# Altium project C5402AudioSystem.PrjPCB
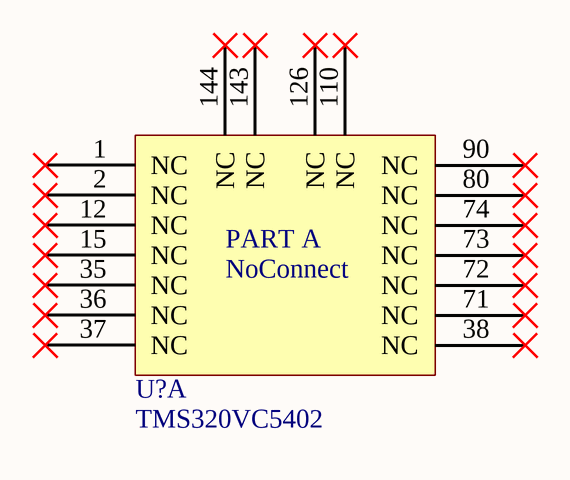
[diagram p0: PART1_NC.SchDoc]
5 sheets, 5 parts. Net scope: global (net labels, ports and power ports of the same name join across sheets).
Sheets:
  PART1_NC.SchDoc
  PART2_PowerSupply.SchDoc
  PART3_Memory.SchDoc
  PART4_Basic.SchDoc
  PART5_HPI_McBSP.SchDoc

## Sheet PART1_NC.SchDoc: 非连接件
size A4; Author: 崔 敖; 李尚文; SheetNumber: 1

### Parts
(Parts that share a designator on the sheet are numbered #1, #2 ... from top to bottom, then left to right.)
U?#1  TMS320VC5402  [TMS320VC5401_PQFP144]  (part A of 5)

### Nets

Not connected (* = marked no-connect by the designer): U?#1 1(NC)* 2(NC)* 12(NC)* 15(NC)* 35(NC)* 36(NC)* 37(NC)* 38(NC)* 71(NC)* 72(NC)* 73(NC)* 74(NC)* 80(NC)* 90(NC)* 110(NC)* 126(NC)* 143(NC)* 144(NC)*

## Sheet PART2_PowerSupply.SchDoc
size A4
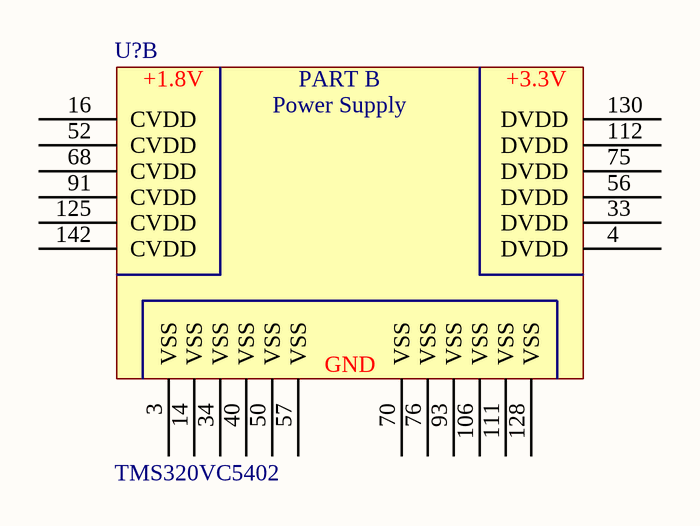
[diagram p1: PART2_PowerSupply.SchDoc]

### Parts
(Parts that share a designator on the sheet are numbered #1, #2 ... from top to bottom, then left to right.)
U?#2  TMS320VC5402  [TMS320VC5401_PQFP144]  (part B of 5)

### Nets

Not connected (* = marked no-connect by the designer): U?#2 3(VSS) 4(DVDD) 14(VSS) 16(CVDD) 33(DVDD) 34(VSS) 40(VSS) 50(VSS) 52(CVDD) 56(DVDD) 57(VSS) 68(CVDD) 70(VSS) 75(DVDD) 76(VSS) 91(CVDD) 93(VSS) 106(VSS) 111(VSS) 112(DVDD) 125(CVDD) 128(VSS) 130(DVDD) 142(CVDD)

## Sheet PART3_Memory.SchDoc
size A4
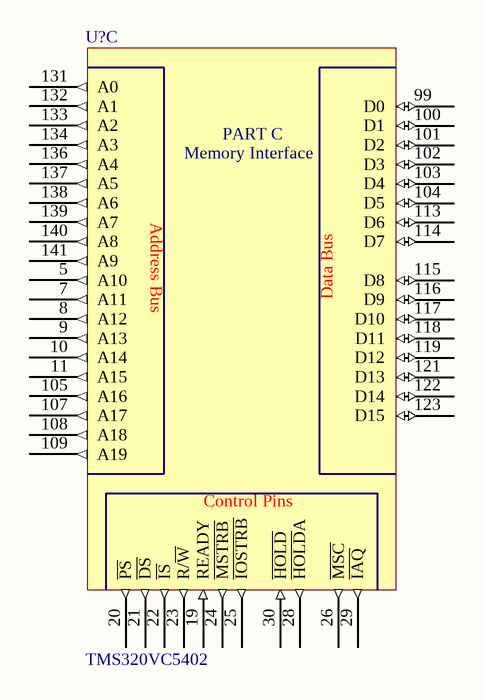
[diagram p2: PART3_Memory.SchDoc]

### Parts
(Parts that share a designator on the sheet are numbered #1, #2 ... from top to bottom, then left to right.)
U?#3  TMS320VC5402  [TMS320VC5401_PQFP144]  (part C of 5)

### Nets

Not connected (* = marked no-connect by the designer): U?#3 5(A10) 7(A11) 8(A12) 9(A13) 10(A14) 11(A15) 19(READY) 20(~{PS}) 21(~{DS}) 22(~{IS}) 23(R/~{W}) 24(~{MSTRB}) 25(~{IOSTRB}) 26(~{MSC}) 28(~{HOLD}A) 29(~{IAQ}) 30(~{HOLD}) 99(D0) 100(D1) 101(D2) 102(D3) 103(D4) 104(D5) 105(A16) 107(A17) 108(A18) 109(A19) 113(D6) 114(D7) 115(D8) 116(D9) 117(D10) 118(D11) 119(D12) 121(D13) 122(D14) 123(D15) 131(A0) 132(A1) 133(A2) 134(A3) 136(A4) 137(A5) 138(A6) 139(A7) 140(A8) 141(A9)

## Sheet PART4_Basic.SchDoc
size A4
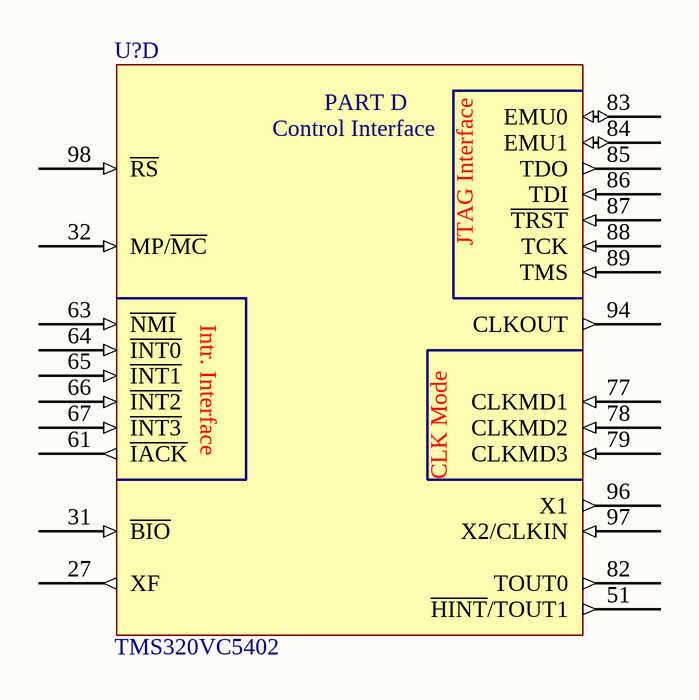
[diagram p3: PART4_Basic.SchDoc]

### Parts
(Parts that share a designator on the sheet are numbered #1, #2 ... from top to bottom, then left to right.)
U?#4  TMS320VC5402  [TMS320VC5401_PQFP144]  (part D of 5)

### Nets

Not connected (* = marked no-connect by the designer): U?#4 27(XF) 31(~{BIO}) 32(MP/~{MC}) 51(~{HINT}/TOUT1) 61(~{IACK}) 63(~{NMI}) 64(~{INT0}) 65(~{INT1}) 66(~{INT2}) 67(~{INT3}) 77(CLKMD1) 78(CLKMD2) 79(CLKMD3) 82(TOUT0) 83(EMU0) 84(EMU1) 85(TDO) 86(TDI) 87(~{TRST}) 88(TCK) 89(TMS) 94(CLKOUT) 96(X1) 97(X2/CLKIN) 98(~{RS})

## Sheet PART5_HPI_McBSP.SchDoc
size A4
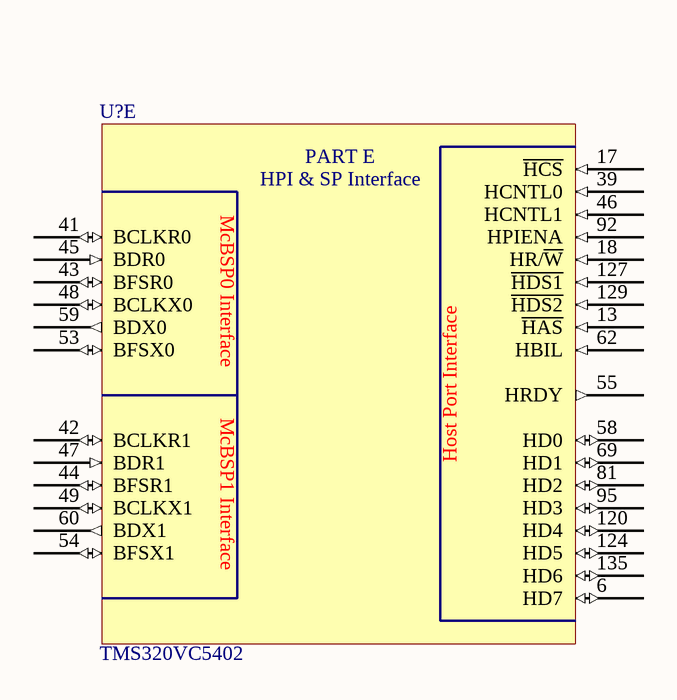
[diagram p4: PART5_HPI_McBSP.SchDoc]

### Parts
(Parts that share a designator on the sheet are numbered #1, #2 ... from top to bottom, then left to right.)
U?#5  TMS320VC5402  [TMS320VC5401_PQFP144]  (part E of 5)

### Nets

Not connected (* = marked no-connect by the designer): U?#5 6(HD7) 13(~{HAS}) 17(~{HCS}) 18(HR/~{W}) 39(HCNTL0) 41(BCLKR0) 42(BCLKR1) 43(BFSR0) 44(BFSR1) 45(BDR0) 46(HCNTL1) 47(BDR1) 48(BCLKX0) 49(BCLKX1) 53(BFSX0) 54(BFSX1) 55(HRDY) 58(HD0) 59(BDX0) 60(BDX1) 62(HBIL) 69(HD1) 81(HD2) 92(HPIENA) 95(HD3) 120(HD4) 124(HD5) 127(~{HDS1}) 129(~{HDS2}) 135(HD6)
